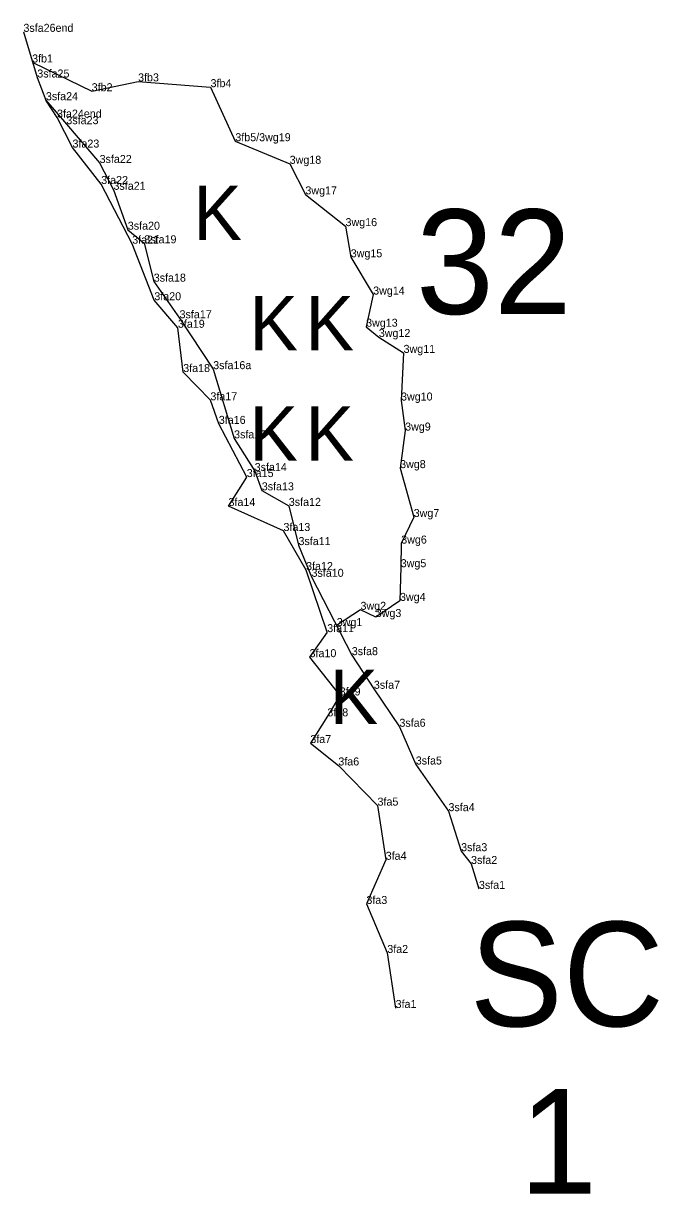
# Model space of a CAD drawing. Extents: x 2072529 to 2268812, y 436423 to 470008.
# Drawn here: x 2096855 to 2097252, y 457983 to 458714 of the extents above; entities that cross this region are included whole.
import ezdxf

# ---------------------------------------------------------------- set-up
doc = ezdxf.new("R2010")
doc.units = 0
for name, color, linetype in [('Old_Level_10', 7, 'Continuous'), ('Old_Level_20', 7, 'Continuous'), ('Old_Level_52', 7, 'Continuous'), ('Old_Level_55', 7, 'Continuous'), ('Old_Level_60', 7, 'Continuous'), ('Old_Level_62', 7, 'Continuous')]:
    doc.layers.add(name, color=color, linetype=linetype)

msp = doc.modelspace()

# ---------------------------------------------------------------- linework, layer by layer
at = {"layer": 'Old_Level_10'}
msp.add_lwpolyline([(2096855.044, 458709.168), (2096863.704, 458680.626), (2096869.092, 458666.443), (2096881.862, 458651.449), (2096902.637, 458627.218), (2096911.291, 458610.451), (2096920.24, 458585.51), (2096930.545, 458577.021), (2096936.442, 458553.054), (2096952.578, 458530.175), (2096973.586, 458498.367), (2096986.61, 458455.106), (2096999.482, 458434.685), (2097003.902, 458422.62), (2097020.798, 458412.921), (2097026.851, 458388.411), (2097034.989, 458368.605), (2097060.119, 458319.635), (2097073.925, 458298.623), (2097089.883, 458274.879), (2097100.089, 458251.298), (2097120.536, 458222.139), (2097128.413, 458197.134), (2097134.629, 458189.141), (2097139.551, 458173.55)], dxfattribs=at)
at = {"layer": 'Old_Level_20'}
for p, q in [((2096855.044, 458709.168), (2096855.044, 458709.168)), ((2096860.826, 458690.074), (2096860.826, 458690.074)), ((2096863.704, 458680.626), (2096863.704, 458680.626)), ((2096926.661, 458678.201), (2096926.661, 458678.201)), ((2096971.937, 458674.584), (2096971.937, 458674.584)), ((2096869.092, 458666.443), (2096869.092, 458666.443)), ((2096897.682, 458672.057), (2096897.682, 458672.057)), ((2096876.037, 458655.57), (2096876.037, 458655.57)), ((2096881.862, 458651.449), (2096881.862, 458651.449)), ((2096885.701, 458636.841), (2096885.701, 458636.841)), ((2096987.393, 458640.81), (2096987.393, 458640.81)), ((2096902.637, 458627.218), (2096902.637, 458627.218)), ((2097021.343, 458626.698), (2097021.343, 458626.698)), ((2096903.614, 458614.064), (2096903.614, 458614.064)), ((2096911.291, 458610.451), (2096911.291, 458610.451)), ((2097031.155, 458607.58), (2097031.155, 458607.58)), ((2096920.24, 458585.51), (2096920.24, 458585.51)), ((2097056.24, 458587.736), (2097056.24, 458587.736)), ((2096922.991, 458576.774), (2096922.991, 458576.774)), ((2096930.545, 458577.021), (2096930.545, 458577.021)), ((2097059.479, 458568.274), (2097059.479, 458568.274)), ((2096936.442, 458553.054), (2096936.442, 458553.054)), ((2097073.495, 458544.994), (2097073.495, 458544.994)), ((2096936.805, 458541.421), (2096936.805, 458541.421)), ((2096952.578, 458530.175), (2096952.578, 458530.175)), ((2096951.548, 458524.227), (2096951.548, 458524.227)), ((2097069.087, 458524.877), (2097069.087, 458524.877)), ((2097077.011, 458518.455), (2097077.011, 458518.455)), ((2097092.48, 458508.523), (2097092.48, 458508.523)), ((2096973.586, 458498.367), (2096973.586, 458498.367)), ((2096954.86, 458496.554), (2096954.86, 458496.554)), ((2096971.833, 458478.913), (2096971.833, 458478.913)), ((2097090.889, 458478.762), (2097090.889, 458478.762)), ((2096977.088, 458464.16), (2096977.088, 458464.16)), ((2096986.61, 458455.106), (2096986.61, 458455.106)), ((2097093.465, 458459.98), (2097093.465, 458459.98)), ((2096999.482, 458434.685), (2096999.482, 458434.685)), ((2097090.319, 458436.514), (2097090.319, 458436.514)), ((2096994.524, 458430.923), (2096994.524, 458430.923)), ((2097003.902, 458422.62), (2097003.902, 458422.62)), ((2096983.134, 458412.824), (2096983.134, 458412.824)), ((2097020.798, 458412.921), (2097020.798, 458412.921)), ((2097098.794, 458405.966), (2097098.794, 458405.966)), ((2097017.469, 458397.222), (2097017.469, 458397.222)), ((2097026.851, 458388.411), (2097026.851, 458388.411)), ((2097091.02, 458389.362), (2097091.02, 458389.362)), ((2097090.702, 458374.601), (2097090.702, 458374.601)), ((2097031.604, 458372.816), (2097031.604, 458372.816)), ((2097034.989, 458368.605), (2097034.989, 458368.605)), ((2097090.229, 458353.532), (2097090.229, 458353.532)), ((2097065.583, 458347.965), (2097065.583, 458347.965)), ((2097050.529, 458338.258), (2097050.529, 458338.258)), ((2097075.101, 458343.453), (2097075.101, 458343.453)), ((2097044.798, 458334.025), (2097044.798, 458334.025)), ((2097033.772, 458318.368), (2097033.772, 458318.368)), ((2097060.119, 458319.635), (2097060.119, 458319.635)), ((2097052.569, 458294.462), (2097052.569, 458294.462)), ((2097073.925, 458298.623), (2097073.925, 458298.623)), ((2097044.898, 458281.404), (2097044.898, 458281.404)), ((2097089.883, 458274.879), (2097089.883, 458274.879)), ((2097034.254, 458264.71), (2097034.254, 458264.71)), ((2097051.739, 458250.698), (2097051.739, 458250.698)), ((2097100.089, 458251.298), (2097100.089, 458251.298)), ((2097076.218, 458225.603), (2097076.218, 458225.603)), ((2097120.536, 458222.139), (2097120.536, 458222.139)), ((2097081.317, 458191.76), (2097081.317, 458191.76)), ((2097128.413, 458197.134), (2097128.413, 458197.134)), ((2097134.629, 458189.141), (2097134.629, 458189.141)), ((2097139.551, 458173.55), (2097139.551, 458173.55)), ((2097069.264, 458164.154), (2097069.264, 458164.154)), ((2097082.301, 458133.522), (2097082.301, 458133.522)), ((2097087.506, 458099.119), (2097087.506, 458099.119))]:
    msp.add_line(p, q, dxfattribs=at)
at = {"layer": 'Old_Level_52'}
for points in [[(2096860.826, 458690.074), (2096897.682, 458672.057), (2096926.661, 458678.201), (2096971.937, 458674.584), (2096987.393, 458640.81), (2097021.343, 458626.698), (2097031.155, 458607.58), (2097056.24, 458587.736), (2097059.479, 458568.274), (2097073.495, 458544.994), (2097069.087, 458524.877), (2097077.011, 458518.455), (2097092.48, 458508.523), (2097090.889, 458478.762), (2097093.465, 458459.98), (2097090.319, 458436.514), (2097098.794, 458405.966), (2097091.02, 458389.362), (2097090.702, 458374.601), (2097090.229, 458353.532), (2097075.101, 458343.453), (2097065.583, 458347.965), (2097050.529, 458338.258)], [(2097044.798, 458334.025), (2097031.604, 458372.816), (2097017.469, 458397.222), (2096983.134, 458412.824), (2096994.524, 458430.923), (2096977.088, 458464.16), (2096971.833, 458478.913), (2096954.86, 458496.554), (2096951.548, 458524.227), (2096936.805, 458541.421), (2096922.991, 458576.774), (2096903.614, 458614.064), (2096885.701, 458636.841), (2096876.037, 458655.57), (2096869.092, 458666.443)], [(2097044.798, 458334.025), (2097033.772, 458318.368), (2097052.569, 458294.462), (2097044.898, 458281.404), (2097034.254, 458264.71), (2097051.739, 458250.698), (2097076.218, 458225.603), (2097081.317, 458191.76), (2097069.264, 458164.154), (2097082.301, 458133.522), (2097087.506, 458099.119)]]:
    msp.add_lwpolyline(points, dxfattribs=at)

# ---------------------------------------------------------------- texts
at = {"layer": 'Old_Level_55'}
for p in [(2096961.198, 458579.104), (2096996.198, 458510.104), (2097031.198, 458510.104), (2096996.198, 458441.104), (2097031.198, 458441.104), (2097046.279, 458276.524)]:
    msp.add_text('K', height=34, dxfattribs=at).set_placement(p)
at = {"layer": 'Old_Level_60'}
for s, p in [('3sfa26end', (2096855.044, 458709.168)), ('3fb1', (2096860.487, 458690.02)), ('3sfa25', (2096863.704, 458680.626)), ('3fb3', (2096926.661, 458678.201)), ('3fb2', (2096897.682, 458672.057)), ('3fb4', (2096971.937, 458674.584)), ('3sfa24', (2096869.092, 458666.443)), ('3fa24end', (2096876.037, 458655.57)), ('3sfa23', (2096881.862, 458651.449)), ('3fb5/3wg19', (2096987.393, 458640.81)), ('3fa23', (2096885.701, 458636.841)), ('3sfa22', (2096902.637, 458627.218)), ('3wg18', (2097021.343, 458626.698)), ('3fa22', (2096903.614, 458614.064)), ('3sfa21', (2096911.291, 458610.451)), ('3wg17', (2097031.155, 458607.58)), ('3wg16', (2097056.24, 458587.736)), ('3sfa20', (2096920.24, 458585.51)), ('3fa21', (2096922.991, 458576.774)), ('3sfa19', (2096930.545, 458577.021)), ('3wg15', (2097059.479, 458568.274)), ('3sfa18', (2096936.442, 458553.054)), ('3wg14', (2097073.495, 458544.994)), ('3fa20', (2096936.805, 458541.421)), ('3sfa17', (2096952.578, 458530.175)), ('3fa19', (2096951.548, 458524.227)), ('3wg13', (2097069.087, 458524.877)), ('3wg12', (2097077.011, 458518.455)), ('3wg11', (2097092.48, 458508.523)), ('3fa18', (2096954.86, 458496.554)), ('3sfa16a', (2096973.586, 458498.367)), ('3fa17', (2096971.833, 458478.913)), ('3wg10', (2097090.889, 458478.762)), ('3fa16', (2096977.088, 458464.16)), ('3wg9', (2097093.465, 458459.98)), ('3sfa15', (2096986.61, 458455.106)), ('3sfa14', (2096999.482, 458434.685)), ('3wg8', (2097090.319, 458436.514)), ('3fa15', (2096994.524, 458430.923)), ('3sfa13', (2097003.902, 458422.62)), ('3fa14', (2096983.134, 458412.824)), ('3sfa12', (2097020.798, 458412.921)), ('3wg7', (2097098.794, 458405.966)), ('3fa13', (2097017.469, 458397.222)), ('3sfa11', (2097026.851, 458388.411)), ('3wg6', (2097091.02, 458389.362)), ('3fa12', (2097031.604, 458372.816)), ('3sfa10', (2097034.989, 458368.605)), ('3wg5', (2097090.702, 458374.601)), ('3wg2', (2097065.583, 458347.965)), ('3wg4', (2097090.229, 458353.532)), ('3wg3', (2097075.101, 458343.453)), ('3fa11', (2097044.798, 458334.025)), ('3wg1', (2097050.748, 458337.819)), ('3fa10', (2097033.772, 458318.368)), ('3sfa8', (2097060.119, 458319.635)), ('3sfa7', (2097073.925, 458298.623)), ('3fa9', (2097052.569, 458294.462)), ('3fa8', (2097044.898, 458281.404)), ('3sfa6', (2097089.883, 458274.879)), ('3fa7', (2097034.254, 458264.71)), ('3sfa5', (2097100.089, 458251.298)), ('3fa6', (2097051.739, 458250.698)), ('3fa5', (2097076.218, 458225.603)), ('3sfa4', (2097120.536, 458222.139)), ('3sfa3', (2097128.413, 458197.134)), ('3fa4', (2097081.317, 458191.76)), ('3sfa2', (2097134.629, 458189.141)), ('3sfa1', (2097139.551, 458173.55)), ('3fa3', (2097069.264, 458164.154)), ('3fa2', (2097082.301, 458133.522)), ('3fa1', (2097087.506, 458099.119))]:
    msp.add_text(s, height=5, dxfattribs=at).set_placement(p)
at = {"layer": 'Old_Level_62'}
for s, p in [('32', (2097100.259, 458532.84)), ('SC', (2097133.708, 458087.687)), ('1', (2097164.813, 457983.143))]:
    msp.add_text(s, height=65.34, dxfattribs=at).set_placement(p)

doc.saveas('drawing.dxf')
